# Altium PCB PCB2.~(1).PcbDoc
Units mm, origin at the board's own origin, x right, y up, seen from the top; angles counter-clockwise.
Board outline 152.4 x 101.6 mm, 2 copper layers (Top Layer, Bottom Layer); 21 components, 0 nets, 133 pads, 0 vias.
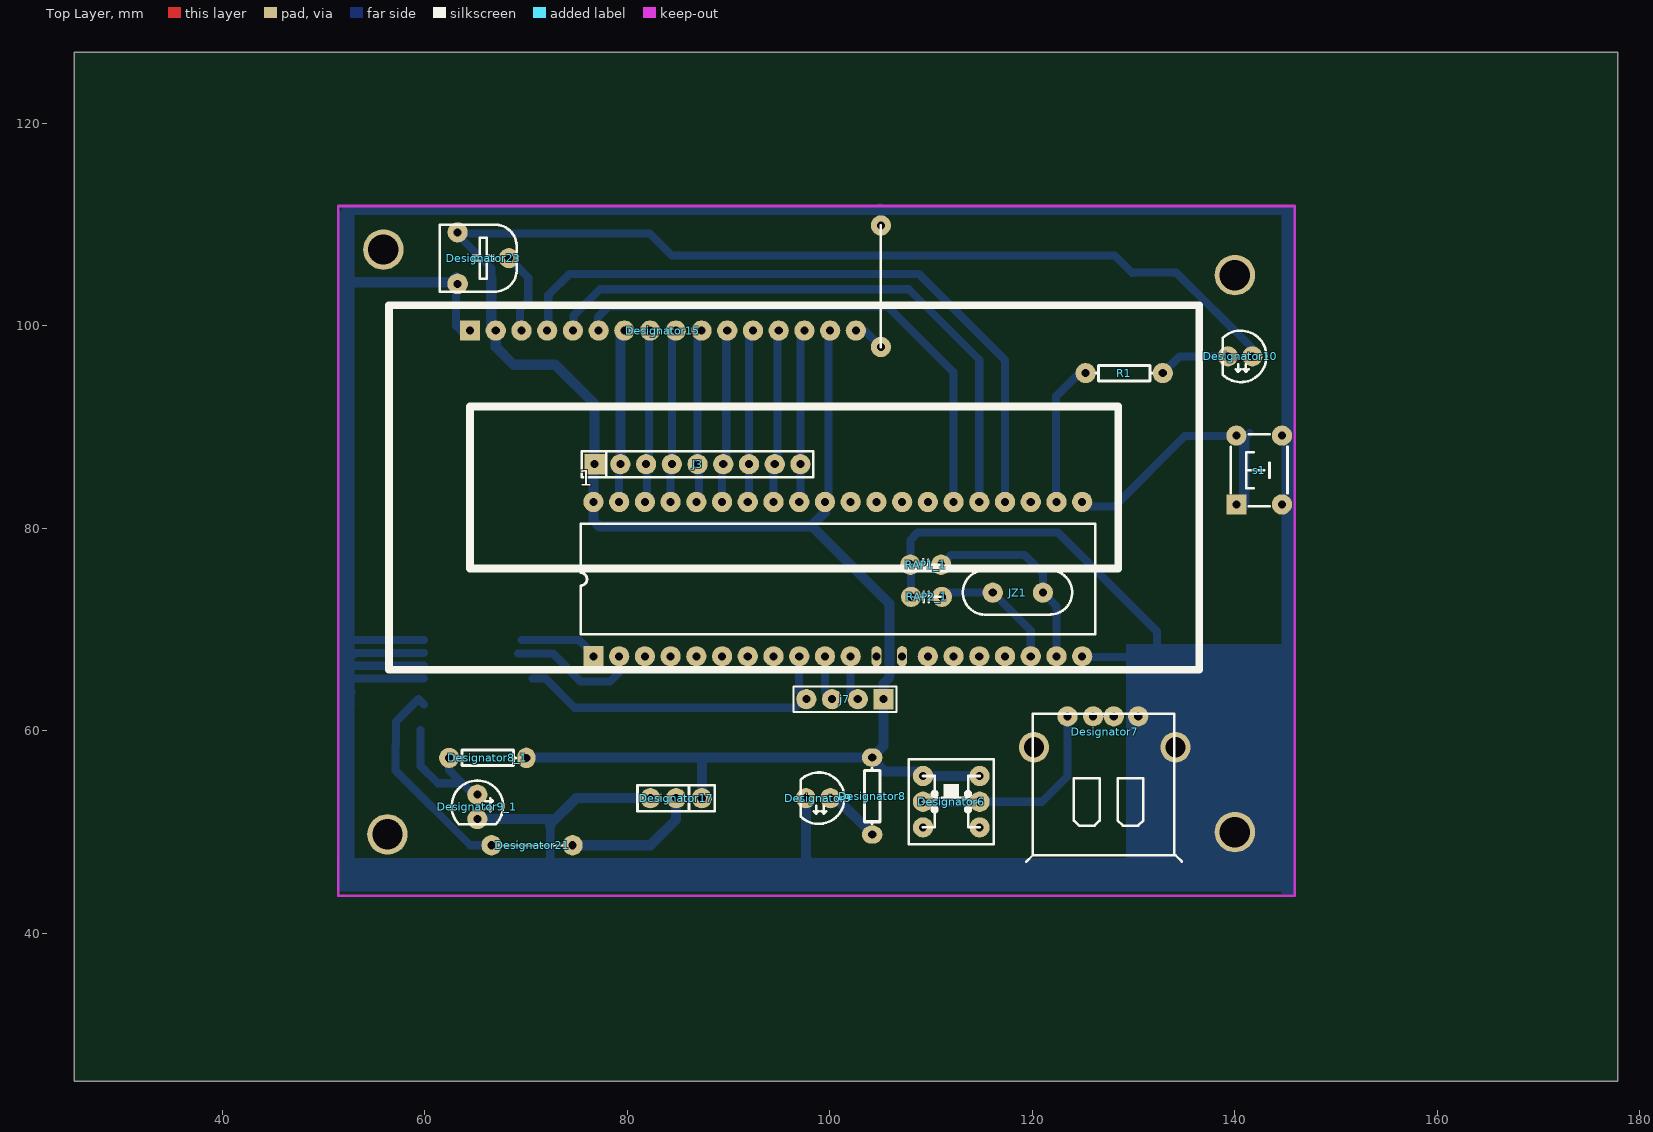
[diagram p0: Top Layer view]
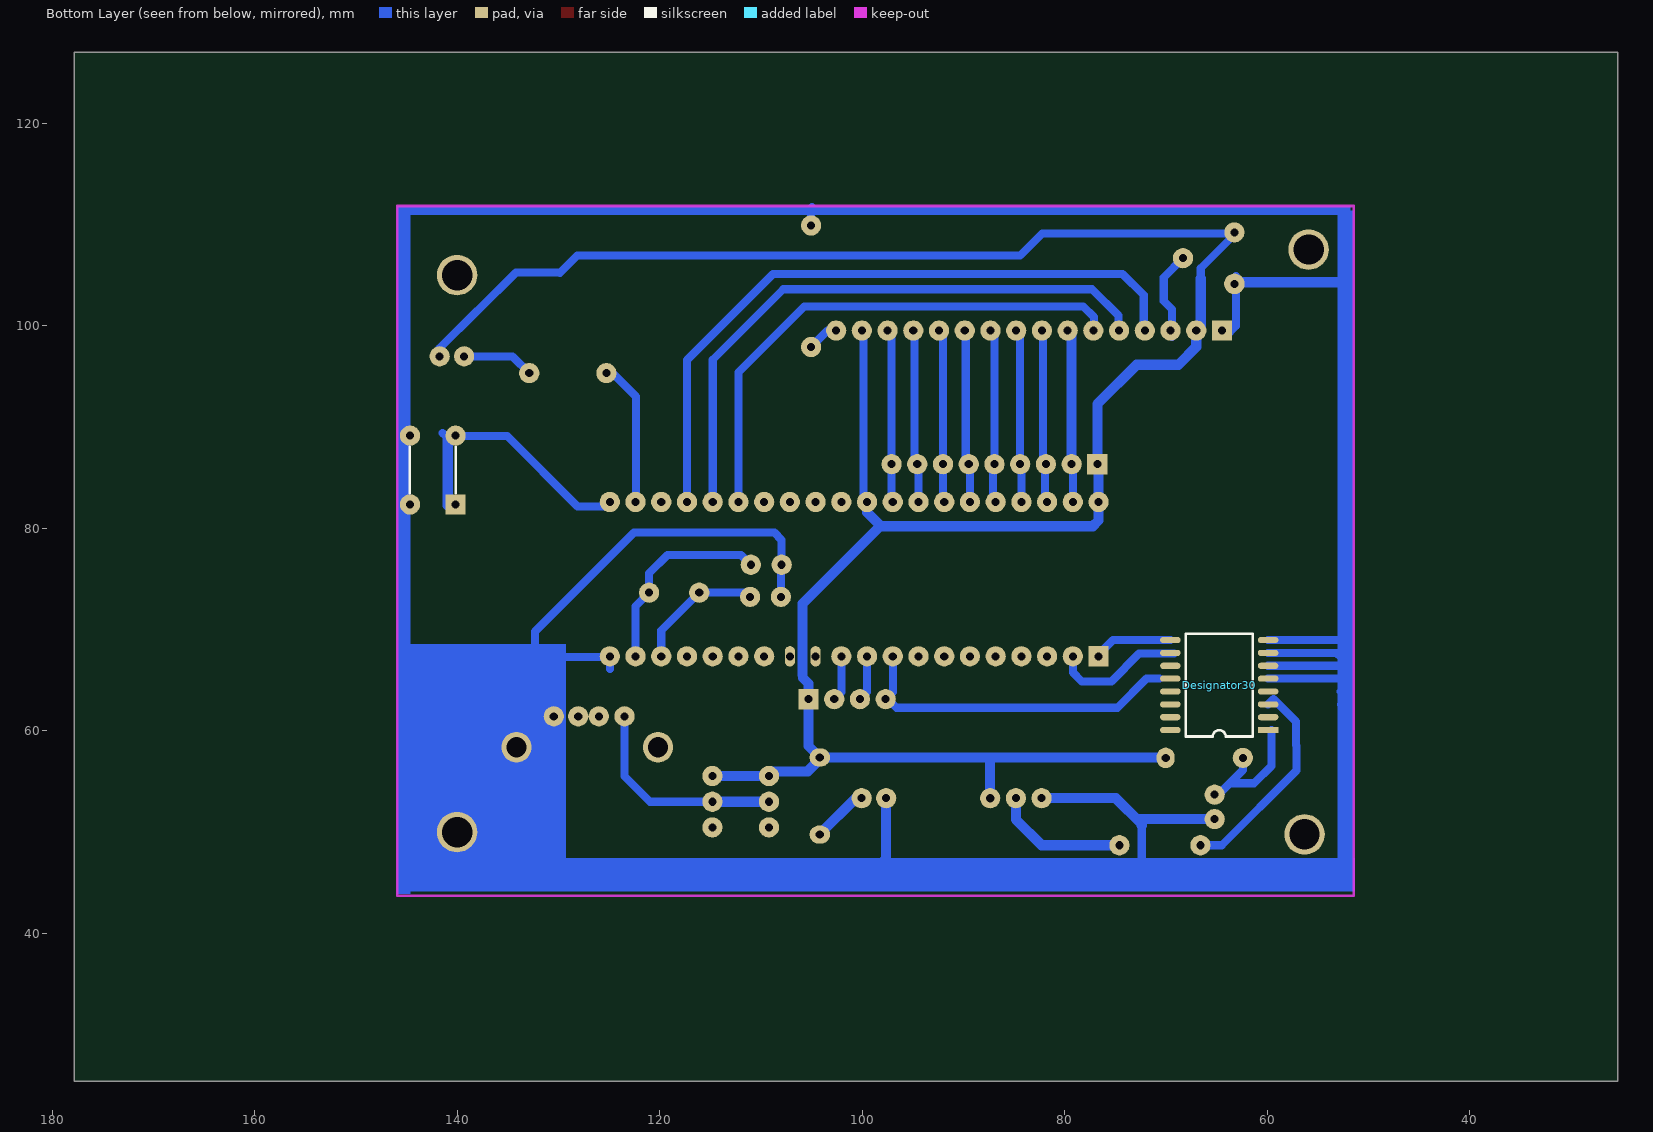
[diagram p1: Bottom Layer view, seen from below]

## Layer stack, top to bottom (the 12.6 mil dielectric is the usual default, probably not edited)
Top Solder: solder mask 0.0102, Solder Resist, Dk 3.5
Top Layer: signal copper 0.0356
Dielectric1: dielectric 0.32, FR-4, Dk 4.8
Bottom Layer: signal copper 0.0356
Bottom Solder: solder mask 0.0102, Solder Resist, Dk 3.5

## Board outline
25.4,25.4 177.8,25.4 177.8,127 25.4,127

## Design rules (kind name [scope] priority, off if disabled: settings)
Clearance [All] p1: gap=0.254
FabricationTestpoint [(IsPad And (OnTopLayer Or OnBottomLayer))] p1: side=3 testpointundercomponent=TRUE minsize=1.016 maxsize=2.54 preferedsize=1.524 minholesize=0 maxholesize=1.016 preferedholesize=0.813 testpointgrid=0.025 allowsidetop=TRUE allowsidebottom=TRUE usegrid=TRUE gridtolerance=0
PolygonConnect [All] p1: connectstyle=Relief reliefconductorwidth=0.254 reliefentries=4 polygonreliefangle="90 Angle" airgapwidth=0.254
RoutingVias [All] p1: holewidth=0.711 width=1.27 viastyle="Through Hole" minholewidth=0.711 minwidth=1.27 maxholewidth=0.711 maxwidth=1.27
SolderMaskExpansion [All] p1: expansion=0.102
Width [All] p1: maxlimit=0.254 minlimit=0.254 preferedwidth=0.254
29 further rules are at their usual default settings.

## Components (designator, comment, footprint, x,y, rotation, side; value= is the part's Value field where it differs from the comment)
1 "89C52" DIP-40 98.125,74.725 r90 top
Designator6 "Comment" AN88 112,53 r0 top
Designator7 "Comment" USB 127.225,54.175 r270 top
Designator8 "Comment" AXIAL0.3#1 104.182,53.563 r270 top
Designator8_1 "Comment" AXIAL0.3#2 66.225,57.325 r0 top
Designator9 "Comment" LED 100.05,53.35 r180 top
Designator9_1 "Comment" LED 65.2,53.7 r270 top
Designator10 "Comment" LED 141.725,96.975 r180 top
Designator15 "Comment" LCD-1602 64.475,99.525 r0 top
Designator17 "Comment" SIP3 84.825,53.35 r180 top
Designator21 "Comment" "Wire - 8mm" 70.6,48.7 r180 top
Designator23 "Comment" RM065 68.325,106.675 r270 top
Designator30 "Comment" SO-16W 59.847,59.999 r0 bottom
J3 "respack" SIP-9A 86.306,86.583 r0 top (schematic designator J1)
j7 "CON4" HDR1X4 102,63 r180 top
JZ1 "晶振" 晶振 118.525,73.7 r180 top
R1 "RES" AXIAL0.3#3 132.875,95.325 r180 top
RAP1_1 "电容" CB1 107.952,76.4 r0 top (schematic designator RAP1)
RAP2_1 "电容" CB1 108.025,73.225 r0 top (schematic designator RAP2)
s1 "0" "TSW DIP-6*6*4.3" 142.4,85.75 r90 top
? "Comment" 跳线 105.05,109.9 r270 top

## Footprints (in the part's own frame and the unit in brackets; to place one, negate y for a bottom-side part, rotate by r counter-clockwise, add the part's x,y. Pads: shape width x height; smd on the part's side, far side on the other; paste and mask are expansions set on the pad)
AN88 [mm]
  round 2 hole 0.8: 1(-2.794,2.54) 2(-2.794,0) 3(-2.794,-2.54) 4(2.794,-2.54) 5(2.794,0) 6(2.794,2.54)
  silkscreen extent -4.19,-4.19 4.19,4.19
AXIAL0.3#1 [mil]
  oval 70x80 hole 32: 1(-150,0) 2(150,0)
  silkscreen extent -109,-30 109,30
AXIAL0.3#2 [mil]
  round 78.74 hole 31.5: 1(-150,0)
  oval 70x80 hole 32: 2(150,0)
  silkscreen extent -109,-30 109,30
AXIAL0.3#3 [mil]
  round 78.74 hole 31.5: 1(0,0) 2(300,0)
  silkscreen extent 41,-30 259,30
CB1 [mm]
  round 2 hole 0.8: 1(0,0) 2(3.048,0)
  silkscreen extent 0,-0.55 3.05,0.52
DIP-40 [mm]
  rect 2x2 hole 0.8: 1(-7.366,21.463)
  round 2 hole 0.8: 2(-7.366,18.923) 3(-7.366,16.383) 4(-7.366,13.843) 5(-7.366,11.303) 6(-7.366,8.763) 7(-7.366,6.223) 8(-7.366,3.683) 9(-7.366,1.143) 10(-7.366,-1.397) 11(-7.366,-3.937) 14(-7.366,-11.557) 15(-7.366,-14.097) 16(-7.366,-16.637) 17(-7.366,-19.177) 18(-7.366,-21.717) 19(-7.366,-24.257) 20(-7.366,-26.797) 21(7.874,-26.797) 22(7.874,-24.257) 23(7.874,-21.717) 24(7.874,-19.177) 25(7.874,-16.637) 26(7.874,-14.097) 27(7.874,-11.557) 28(7.874,-9.017) 29(7.874,-6.477) 30(7.874,-3.937) 31(7.874,-1.397) 32(7.874,1.143) 33(7.874,3.683) 34(7.874,6.223) 35(7.874,8.763) 36(7.874,11.303) 37(7.874,13.843) 38(7.874,16.383) 39(7.874,18.923) 40(7.874,21.463)
  oval 2x1 hole 0.8: 12(-7.366,-6.477) 13(-7.366,-9.017)
  silkscreen extent -5.21,-28.07 5.72,22.73
HDR1X4 [mm]
  rect 2x2 hole 0.8: 1(-3.302,-0.127)
  round 2 hole 0.8: 2(-0.762,-0.127) 3(1.778,-0.127) 4(4.318,-0.127)
  silkscreen extent -4.57,-1.4 5.59,1.14
LCD-1602 [mm] "LCD module 16*2 char"
  rect 2x2 hole 0.8: 1(0,0)
  round 2 hole 0.8: 2(2.54,0) 3(5.08,0) 4(7.62,0) 5(10.16,0) 6(12.7,0) 7(15.24,0) 8(17.78,0) 9(20.32,0) 10(22.86,0) 11(25.4,0) 12(27.94,0) 13(30.48,0) 14(33.02,0) 15(35.56,0) 16(38.1,0)
  silkscreen extent -8,-33.5 72,2.5, body extent -8.15,-33.11 71.85,1.89, height 9
LED [mm]
  round 2 hole 0.8: 1(0,0) 2(2.413,0)
  silkscreen extent -1.4,-2.54 2.94,2.54
RM065 [mm] "蓝白可调电位器"
  round 2 hole 0.8: 1(-2.54,-5.08) 2(0,0)
  round 2.032 hole 0.8: 3(2.54,-5.08)
  silkscreen extent -3.3,-6.86 3.3,0.76, body extent -3.25,-6.83 3.25,0.75, height 7.6
SIP3 [mm]
  round 2 hole 0.813: 1(-2.54,0)
  round 2 hole 0.8: 2(0,0) 3(2.54,0)
  silkscreen extent -3.81,-1.27 3.81,1.27
SIP-9A [mm]
  rect 2x2 hole 0.8: 1(-9.525,-0.254)
  round 2 hole 0.8: 2(-6.985,-0.254) 3(-4.445,-0.254) 4(-1.905,-0.254) 5(0.635,-0.254) 6(3.175,-0.254) 7(5.715,-0.254) 8(8.255,-0.254) 9(10.795,-0.254)
  silkscreen extent -10.79,-1.52 12.06,1.04
SO-16W [mil]
  rect 80x24 smd: 1(3,-3)
  oval 80x24 smd: 2(3,-53) 3(3,-103) 4(3,-153) 5(3,-203) 6(3,-253) 7(3,-303) 8(3,-353) 9(383,-353) 10(383,-303) 11(383,-253) 12(383,-203) 13(383,-153) 14(383,-103) 15(383,-53) 16(383,-3)
  silkscreen extent 63,-378 323,22
"TSW DIP-6*6*4.3" [mm] "6*6*4.3mm"
  rect 2x2 hole 0.8: 1(-3.4,2.25)
  round 2 hole 0.8: 2(-3.4,-2.25) 3(3.4,-2.25) 4(3.4,2.25)
  silkscreen extent -3.56,-2.79 3.56,2.79, body extent -4.11,-3 4.11,3, height 4.25
USB [mm]
  round 2 hole 0.8: +(-7.255,-3.757) -(-7.255,3.228) D1(-7.255,0.815) D2(-7.255,-1.217)
  round 3 hole 2 unplated: VSS(-4.207,6.911) VSS2(-4.207,-7.059)
  silkscreen extent -7.51,-7.82 7.1,7.55
"Wire - 8mm" [mm] "直接：0.5mm，脚距：8mm"
  round 2 hole 0.8: 1(-4,0) 2(4,0)
  silkscreen extent -3,0 3,0, body extent -4.25,-0.25 4.25,0.25, height 0.95
晶振 [mm]
  round 2 hole 0.8: 1(-2.517,0.055) 2(2.436,0.055)
  silkscreen extent -5.41,-2.18 5.39,2.24
跳线 [mm]
  round 2 hole 0.762: 0(0,0) 0(12,0)
  silkscreen extent 0,0 12,0

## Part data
J3: library part CON9, "Connector"
j7: "Connector"
s1: library part 2位拨码开关, "DIP Switch"

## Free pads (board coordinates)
  round 4 hole 3: 0(55.925,107.525) 0(56.325,49.775) 0(140,50) 0(140,105)

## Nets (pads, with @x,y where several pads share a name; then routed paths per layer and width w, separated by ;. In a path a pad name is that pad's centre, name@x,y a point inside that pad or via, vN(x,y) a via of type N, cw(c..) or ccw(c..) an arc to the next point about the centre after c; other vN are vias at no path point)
pads on no net: 1.1 1.2 1.3 1.4 1.5 1.6 1.7 1.8 1.9 1.10 1.11 1.12 1.13 1.14 1.15 1.16 1.17 1.18 1.19 1.20 1.21 1.22 1.23 1.24 1.25 1.26 1.27 1.28 1.29 1.30 1.31 1.32 1.33 1.34 1.35 1.36 1.37 1.38 1.39 1.40 ?.0 Designator6.1 Designator6.2 Designator6.3 Designator6.4 Designator6.5 Designator6.6 Designator7.+ Designator7.- Designator7.D1 Designator7.D2 Designator7.VSS Designator7.VSS2 Designator8.1 Designator8.2 Designator8_1.1 Designator8_1.2 Designator9.1 Designator9.2 Designator9_1.1 Designator9_1.2 Designator10.1 Designator10.2 Designator15.1 Designator15.2 Designator15.3 Designator15.4 Designator15.5 Designator15.6 Designator15.7 Designator15.8 Designator15.9 Designator15.10 Designator15.11 Designator15.12 Designator15.13 Designator15.14 Designator15.15 Designator15.16 Designator17.1 Designator17.2 Designator17.3 Designator21.1 Designator21.2 Designator23.1 Designator23.2 Designator23.3 Designator30.1 Designator30.2 Designator30.3 Designator30.4 Designator30.5 Designator30.6 Designator30.7 Designator30.8 Designator30.9 Designator30.10 Designator30.11 Designator30.12 Designator30.13 Designator30.14 Designator30.15 Designator30.16 J3.1 J3.2 J3.3 J3.4 J3.5 J3.6 J3.7 J3.8 J3.9 j7.1 j7.2 j7.3 j7.4 JZ1.1 JZ1.2 R1.1 R1.2 RAP1_1.1 RAP1_1.2 RAP2_1.1 RAP2_1.2 s1.1 s1.2 s1.3 s1.4
copper on no net: | length 912.1
  Bottom Layer w0.8: 52.025,65.475 52.345,65.155 59.923,65.155 ; 52.1,61.45 52.205,61.345 ; 52.25,66.6 52.425,66.425 59.923,66.425 ; 52.45,64.225 52.79,63.885 ; 52.6,62.75 52.735,62.615 ; 52.69,68.965 59.923,68.965 ; 52.975,67.475 53.195,67.695 59.923,67.695 ; 59.6,60.075 59.6,56.525 61.3,54.825 63.55,54.825 ; 59.923,62.615 59.394,63.144 57.175,60.925 57.175,58.597 57.1,58.522 57.1,56.1 64.5,48.7 66.6,48.7 ; 62.873,109.377 66.575,105.675 66.575,104.675 ; 63.11,104.895 63.11,99.965 64.075,99 ; 63.125,109.425 63.125,109.335 63.36,109.1 82.225,109.1 84.4,106.925 128.135,106.925 129.827,105.233 134.188,105.258 141.721,97.811 141.725,97.2 ; 65.175,53.375 62.415,56.135 ; 66.575,99.425 66.75,99.25 ; 68.325,106.675 70.225,104.775 70.225,102.45 69.4,101.625 69.4,98.9 ; 69.225,67.625 72.65,67.625 75.4,64.875 78.325,64.875 79.202,65.752 79.202,67.359 ; 69.575,68.965 75.235,68.965 76.662,67.538 76.662,67.359 ; 70.65,65.155 71.92,65.155 74.8,62.275 96.625,62.275 97.477,63.127 ; 71.65,45.525 72.4,46.275 72.4,50.65 ; 72.195,99.805 72.195,103.02 74.3,105.125 108.6,105.125 108.8,105.125 117.302,96.623 117.302,82.599 ; 74.7,99.7 74.7,101 77.3,103.6 107.725,103.6 107.8,103.6 114.762,96.638 114.762,82.599 ; 77.125,99.3 77.125,100.85 78.175,101.9 105.325,101.9 105.725,101.9 112.222,95.403 112.222,82.599 ; 79.202,82.149 79.202,86.21 ; 79.321,99.746 79.375,99.8 ; 81.95,82.357 81.95,86.55 ; 82.155,86.623 82.155,99.8 ; 84.282,82.149 84.282,86.21 ; 84.401,86.329 84.401,99.506 84.695,99.8 ; 86.941,86.329 86.941,99.506 ; 87.075,82.402 87.075,86.475 ; 89.362,82.149 89.362,86.21 ; 89.775,86.623 89.775,99.8 ; 92.021,82.268 92.021,86.329 92.021,99.506 ; 94.442,82.149 94.442,86.21 ; 94.855,86.623 94.855,99.8 ; 96.974,67.279 96.974,63.835 97.682,63.127 ; 97.101,82.268 97.101,86.329 97.101,99.101 97.395,99.395 ; 99.514,67.279 99.514,63.835 100.222,63.127 ; 99.522,82.9 100.025,82.397 ; 99.86,82.912 99.86,99.425 ; 102.054,67.279 102.054,63.835 102.762,63.127 ; 102.575,99.525 103.425,99.525 105.05,97.9 ; 104.975,111.7 105.05,111.625 105.05,109.9 ; 108.025,73.225 108.025,76.327 107.952,76.4 107.952,78.852 108.675,79.575 122.55,79.575 132.325,69.8 132.325,68.175 132.6,67.9 ; 111,76.4 111.975,77.375 119.225,77.375 121.042,75.558 121.042,73.645 122.382,72.305 122.382,67.359 ; 111.073,73.225 111.493,73.645 116.089,73.645 119.842,69.892 119.842,67.359 ; 114.794,53 120.95,53 123.468,55.518 123.468,61.43 ; 116.517,73.583 116.517,73.72 ; 119.926,67.35 119.975,67.35 ; 122.325,82.325 122.325,93.011 124.614,95.3 ; 124.914,66.086 124.914,67.279 129.821,67.279 ; 124.922,82.149 128.099,82.149 135.05,89.1 141.125,89.1 141.45,89.425 ; 130.453,61.43 130.453,61.828 ; 132.875,95.325 134.525,96.975 139.312,96.975 ; 140.625,82.65 140.85,82.425 ; 62.415,56.135 62.415,57.325 62.415,56.135 ; 124.922,67.153 124.922,67.359 124.922,67.153
  Bottom Layer w1: 52.65,104.425 52.775,104.3 63.11,104.3 ; 65.2,51.287 72.538,51.287 72.675,51.15 ; 66.575,104.675 66.575,99.965 67.015,99.525 67.015,97.91 68.775,96.15 72.9,96.15 76.781,92.269 76.781,86.329 ; 70.083,57.373 82.442,57.373 88.227,57.373 104.182,57.373 105.302,58.493 105.302,63.127 105.302,64.677 105.85,65.225 ; 72.4,50.65 72.4,50.8 74.95,53.35 82.285,53.35 ; 74.6,48.7 82.275,48.7 84.825,51.25 84.825,53.35 ; 76.781,86.494 76.781,86.329 ; 79.321,86.329 79.321,99.131 79.715,99.525 ; 87.365,53.35 87.365,57.19 87.375,57.2 ; 97.637,53.35 97.637,47.388 97.775,47.25 ; 99.522,82.599 99.522,81.572 98.153,80.203 ; 100.585,53.35 100.05,53.35 100.65,53.35 104.182,49.818 104,50 ; 104,57.373 105.373,56 109,56 109.46,55.54 114.794,55.54 ; 105.9,65.5 105.9,72.55 98.247,80.203 98.153,80.203 ; 109.206,53 114.794,53 ; 140.925,89.1 140.925,82.3 140.95,82.275 ; 76.781,86.329 76.662,86.21 76.662,82.599 76.662,80.763 77.222,80.203 98.153,80.203

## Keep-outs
Keep-Out Layer:
  lines w0.254: 51.475,43.725 145.925,43.725 145.925,111.825 51.475,111.825 51.475,43.725

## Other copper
Bottom Layer:
  rectangle: 51.775,110.925 145.925,111.825
  rectangle: 144.625,43.9 145.925,111.5
  rectangle: 51.325,44.125 144.775,47.45
  rectangle: 51.475,47.325 53.075,111.375
  rectangle: 129.25,46.15 145.5,68.575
